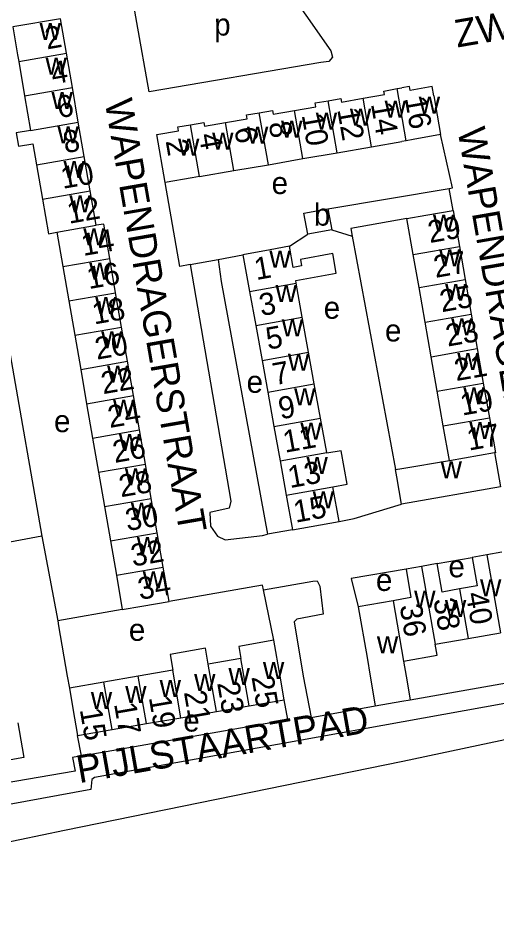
# Model space of a CAD drawing. Extents: x 162883 to 165538, y 383986 to 385172.
# Drawn here: x 164430.6 to 164517.2, y 384254.3 to 384419 of the extents above; entities that cross this region are included whole.
import ezdxf

# ---------------------------------------------------------------- set-up
doc = ezdxf.new("R2010")
doc.units = 0
for name, color, linetype in [('BLT_Basislijn', 7, 'Continuous'), ('BLT_Bebouwing', 7, 'Continuous'), ('BLT_Centroide', 7, 'Continuous'), ('BLT_Huisnummer', 7, 'Continuous'), ('BLT_Huisnummer_ tussenligend', 7, 'Continuous'), ('BLT_Onderverdeling_panden', 7, 'Continuous'), ('BLT_Straatnaam', 7, 'Continuous')]:
    doc.layers.add(name, color=color, linetype=linetype)

msp = doc.modelspace()

# ---------------------------------------------------------------- linework, layer by layer
at = {"layer": 'BLT_Basislijn'}
for p, q in [((164454.29, 384405.7), (164452.06, 384418.28)), ((164485.36, 384411.01), (164454.29, 384405.7)), ((164509.29, 384384.26), (164508.58, 384388.26)), ((164479.71, 384377.78), (164482.99, 384379.97)), ((164487.33, 384380.75), (164491.03, 384379.63)), ((164491.03, 384379.63), (164498.87, 384337.37)), ((164461.74, 384374.47), (164466.77, 384375.41)), ((164466.77, 384375.41), (164471.28, 384376.26)), ((164480.24, 384326.49), (164475.7, 384325.72)), ((164434.9, 384325.32), (164437.76, 384309.99)), ((164506.39, 384320.36), (164512.75, 384321.48)), ((164476.85, 384306.5), (164474.99, 384315.63)), ((164449.44, 384312.07), (164437.76, 384309.99)), ((164501.53, 384295.72), (164537.37, 384302.06)), ((164442.08, 384285.61), (164441.37, 384289.25)), ((164438.99, 384272.13), (164500.18, 384284.61)), ((164379.76, 384259.88), (164438.99, 384272.13))]:
    msp.add_line(p, q, dxfattribs=at)
for points in [[(164452.06, 384418.28), (164451.49, 384421.69), (164451.81, 384423.01), (164453.14, 384423.99), (164474.55, 384427.71), (164476.59, 384427.38), (164478.15, 384426.08), (164487.2, 384413.14), (164487.46, 384412), (164486.84, 384411.19), (164485.36, 384411.01)], [(164508.58, 384388.26), (164509.16, 384388.36), (164507.01, 384397.98)], [(164422.17, 384390.76), (164423.35, 384390.97), (164434.9, 384325.32)], [(164461.74, 384374.47), (164459.85, 384374.11), (164457.21, 384389.3)], [(164486.64, 384384.58), (164508.58, 384388.26)], [(164500.94, 384382.8), (164490.78, 384380.98), (164491.03, 384379.63)], [(164466.77, 384375.41), (164467.34, 384371.42), (164475.7, 384325.72)], [(164461.74, 384374.47), (164469.08, 384331.69), (164468.79, 384330.42), (164465.31, 384329.62), (164465.39, 384327.17), (164466.68, 384325.31), (164468.05, 384324.69), (164474.83, 384325.48), (164475.7, 384325.72)], [(164488.67, 384328.01), (164491.42, 384328.51), (164499.99, 384331.15)], [(164434.9, 384325.32), (164425.15, 384323.55), (164416.49, 384321.97), (164412.07, 384321.15)], [(164500.79, 384319.38), (164490.88, 384317.65), (164492.15, 384312.57)], [(164474.99, 384315.63), (164483.89, 384317.18), (164484.69, 384317.23), (164485.17, 384316.27), (164485.78, 384311.25), (164481, 384310.34), (164480.55, 384309.82), (164482.16, 384300), (164483.59, 384292.55), (164495.22, 384294.64)], [(164474.99, 384315.63), (164474.82, 384316.46), (164457.92, 384313.54)], [(164437.76, 384309.99), (164437.92, 384309.13), (164439.45, 384300), (164439.89, 384297.84)], [(164537.04, 384298.36), (164444.4, 384281.69), (164443.92, 384281.32), (164443.78, 384279.5), (164414.83, 384274.17), (164413.46, 384274.09), (164412.69, 384277.13), (164412.28, 384277.16), (164358.24, 384267.65), (164355.83, 384267.19), (164355.01, 384265.8), (164304.07, 384256.84), (164302.9, 384256.99), (164302.04, 384260.09), (164301.53, 384260.09), (164267.64, 384254.3)], [(164500.18, 384284.61), (164529.46, 384290.85), (164557.72, 384296.7), (164568.34, 384299.01)], [(164442.08, 384285.61), (164479.42, 384292.18), (164478.74, 384295.73)], [(164442.08, 384285.61), (164440.43, 384285.28), (164440.9, 384282.79), (164419.36, 384279.14), (164418.31, 384285.79)]]:
    msp.add_lwpolyline(points, dxfattribs=at)
at = {"layer": 'BLT_Bebouwing'}
for p, q in [((164438.25, 384418.95), (164429.62, 384417.45)), ((164439.33, 384412.71), (164438.25, 384418.95)), ((164430.7, 384411.22), (164431.78, 384404.98)), ((164440.41, 384406.48), (164439.33, 384412.71)), ((164441.49, 384400.25), (164440.41, 384406.48)), ((164496.76, 384405.84), (164499.15, 384406.3)), ((164499.15, 384406.3), (164500, 384406.45)), ((164431.78, 384404.98), (164432.86, 384398.75)), ((164505.79, 384404.97), (164507.01, 384397.98)), ((164442.57, 384394.01), (164441.49, 384400.25)), ((164457.21, 384389.3), (164455.67, 384397.99)), ((164494.56, 384395.79), (164500.01, 384396.73)), ((164500.79, 384396.87), (164500.01, 384396.73)), ((164482.1, 384393.63), (164488.33, 384394.71)), ((164488.33, 384394.71), (164494.56, 384395.79)), ((164443.65, 384387.78), (164442.57, 384394.01)), ((164475.87, 384392.54), (164482.1, 384393.63)), ((164433.94, 384392.52), (164435.02, 384386.29)), ((164463.41, 384390.38), (164469.64, 384391.46)), ((164469.64, 384391.46), (164475.87, 384392.54)), ((164444.73, 384381.57), (164443.65, 384387.78)), ((164486.64, 384384.58), (164487.33, 384380.75)), ((164509.29, 384384.26), (164510.43, 384377.76)), ((164437.62, 384380.31), (164438.69, 384374.11)), ((164487.33, 384380.75), (164482.99, 384379.97)), ((164510.43, 384377.76), (164511.48, 384371.76)), ((164448.24, 384369.37), (164447.17, 384375.58)), ((164471.28, 384376.26), (164472.48, 384369.6)), ((164503.13, 384370.3), (164502.08, 384376.3)), ((164438.69, 384374.11), (164439.77, 384367.91)), ((164511.48, 384371.76), (164512.57, 384365.51)), ((164482.01, 384364.95), (164480.9, 384371.11)), ((164504.23, 384364.05), (164503.13, 384370.3)), ((164449.32, 384363.17), (164448.24, 384369.37)), ((164472.48, 384369.6), (164473.59, 384363.44)), ((164439.77, 384367.91), (164440.84, 384361.7)), ((164512.57, 384365.51), (164513.67, 384359.26)), ((164473.59, 384363.44), (164474.73, 384357.11)), ((164483.15, 384358.62), (164482.01, 384364.95)), ((164505.33, 384357.79), (164504.23, 384364.05)), ((164440.84, 384361.7), (164441.92, 384355.5)), ((164450.39, 384356.97), (164449.32, 384363.17)), ((164484.18, 384352.9), (164483.15, 384358.62)), ((164513.67, 384359.26), (164514.76, 384353.01)), ((164451.46, 384350.76), (164450.39, 384356.97)), ((164474.73, 384357.11), (164475.76, 384351.38)), ((164506.43, 384351.54), (164505.33, 384357.79)), ((164441.92, 384355.5), (164442.99, 384349.29)), ((164485.31, 384346.68), (164484.18, 384352.9)), ((164514.76, 384353.01), (164515.86, 384346.76)), ((164452.54, 384344.56), (164451.46, 384350.76)), ((164475.76, 384351.38), (164476.88, 384345.16)), ((164507.52, 384345.29), (164506.43, 384351.54)), ((164442.99, 384349.29), (164444.07, 384343.09)), ((164486.43, 384340.46), (164485.31, 384346.68)), ((164508.62, 384339.04), (164507.52, 384345.29)), ((164453.62, 384338.35), (164452.54, 384344.56)), ((164476.88, 384345.16), (164478, 384338.94)), ((164444.07, 384343.09), (164445.14, 384336.89)), ((164478, 384338.94), (164479.12, 384332.72)), ((164500, 384337.57), (164508.62, 384339.04)), ((164454.69, 384332.15), (164453.62, 384338.35)), ((164498.87, 384337.37), (164500, 384337.57)), ((164445.14, 384336.89), (164446.22, 384330.68)), ((164488.67, 384328.01), (164487.55, 384334.24)), ((164455.77, 384325.95), (164454.69, 384332.15)), ((164479.12, 384332.72), (164480.24, 384326.49)), ((164446.22, 384330.68), (164447.29, 384324.48)), ((164480.24, 384326.49), (164488.67, 384328.01)), ((164456.84, 384319.74), (164455.77, 384325.95)), ((164447.29, 384324.48), (164448.37, 384318.27)), ((164518.1, 384322.42), (164515.42, 384321.95)), ((164515.42, 384321.95), (164512.75, 384321.48)), ((164457.92, 384313.54), (164456.84, 384319.74)), ((164503.59, 384319.87), (164500.79, 384319.38)), ((164506.39, 384320.36), (164503.59, 384319.87)), ((164448.37, 384318.27), (164449.44, 384312.07)), ((164500, 384313.93), (164498.44, 384313.65)), ((164498.44, 384313.65), (164492.15, 384312.57)), ((164492.15, 384312.57), (164493.72, 384303.39)), ((164512.03, 384306.83), (164517.88, 384307.86)), ((164506.05, 384305.79), (164512.03, 384306.83)), ((164470.92, 384303.22), (164464.98, 384302.19)), ((164500.31, 384302.72), (164500.78, 384300)), ((164458.57, 384301.08), (164452.34, 384300)), ((164452.34, 384300), (164446.11, 384298.92)), ((164500.78, 384300), (164501.53, 384295.72)), ((164446.11, 384298.92), (164439.89, 384297.84)), ((164466.47, 384293.6), (164472.4, 384294.63)), ((164472.4, 384294.63), (164478.74, 384295.73)), ((164460.06, 384292.49), (164466.47, 384293.6)), ((164447.6, 384290.33), (164453.83, 384291.41)), ((164453.83, 384291.41), (164460.06, 384292.49)), ((164441.37, 384289.25), (164447.6, 384290.33))]:
    msp.add_line(p, q, dxfattribs=at)
for points in [[(164429.62, 384417.45), (164430.49, 384412.44), (164430.7, 384411.22)], [(164505.79, 384404.97), (164505.49, 384406.68), (164501.51, 384405.98), (164501.38, 384406.7), (164500, 384406.45)], [(164486.69, 384404.11), (164489, 384404.51), (164489.12, 384403.86), (164493.04, 384404.55)], [(164493.04, 384404.55), (164496.87, 384405.21), (164496.76, 384405.84)], [(164480.58, 384402.33), (164484.45, 384403), (164484.33, 384403.7), (164486.69, 384404.11)], [(164468.12, 384400.16), (164472.04, 384400.84), (164471.92, 384401.54), (164474.23, 384401.94)], [(164474.23, 384401.94), (164476.64, 384402.35), (164476.76, 384401.66), (164480.58, 384402.33)], [(164455.67, 384397.99), (164459.59, 384398.68), (164459.47, 384399.36), (164461.77, 384399.77)], [(164461.77, 384399.77), (164464.21, 384400.19), (164464.33, 384399.5), (164468.12, 384400.16)], [(164432.86, 384398.75), (164430.25, 384398.29), (164430.67, 384395.88), (164433.28, 384396.34), (164433.94, 384392.52)], [(164507.01, 384397.98), (164502.09, 384397.1), (164500.79, 384396.87)], [(164463.41, 384390.38), (164462.1, 384390.16), (164457.21, 384389.3)], [(164435.02, 384386.29), (164436.1, 384380.05), (164437.62, 384380.31)], [(164482.99, 384379.97), (164482.3, 384383.79), (164486.64, 384384.58)], [(164500.94, 384382.8), (164504.36, 384383.4), (164509.29, 384384.26)], [(164447.17, 384375.58), (164446.09, 384381.8), (164444.73, 384381.57)], [(164502.08, 384376.3), (164500.94, 384382.8)], [(164479.71, 384377.78), (164476.2, 384377.15), (164471.28, 384376.26)], [(164480.9, 384371.11), (164480.83, 384371.56), (164488.15, 384372.91), (164487.51, 384376.46), (164481.67, 384375.41), (164481.88, 384374.23), (164480.39, 384373.96), (164479.71, 384377.78)], [(164515.86, 384346.76), (164516.96, 384340.42), (164516.77, 384340.47)], [(164487.55, 384334.24), (164490.16, 384334.71), (164489.07, 384340.8), (164486.45, 384340.32), (164486.43, 384340.46)], [(164516.77, 384340.47), (164517.86, 384334.25), (164499.99, 384331.15)], [(164499.99, 384331.15), (164499.1, 384336.07), (164498.87, 384337.37)], [(164512.75, 384321.48), (164513.65, 384316.33), (164510.47, 384315.78)], [(164500.79, 384319.38), (164501.68, 384314.25), (164500, 384313.93)], [(164510.47, 384315.78), (164507.29, 384315.22), (164506.39, 384320.36)], [(164449.44, 384312.07), (164452.99, 384312.68), (164457.92, 384313.54)], [(164476.85, 384306.5), (164470.55, 384305.38), (164470.92, 384303.22)], [(164478.74, 384295.73), (164478, 384300), (164476.85, 384306.5)], [(164500.31, 384302.72), (164506.4, 384303.8), (164506.05, 384305.79)], [(164464.98, 384302.19), (164464.49, 384305.06), (164458.09, 384303.95), (164458.57, 384301.08)], [(164493.72, 384303.39), (164494.3, 384300), (164495.22, 384294.64)], [(164439.89, 384297.84), (164440.52, 384294.18), (164441.37, 384289.25)], [(164495.22, 384294.64), (164500, 384295.46), (164501.53, 384295.72)], [(164430.53, 384291.56), (164430.77, 384290.18), (164431.62, 384285.26), (164423.18, 384283.79), (164422.7, 384286.55), (164418.31, 384285.79)]]:
    msp.add_lwpolyline(points, dxfattribs=at)
at = {"layer": 'BLT_Onderverdeling_panden'}
for p, q in [((164430.7, 384411.22), (164439.33, 384412.71)), ((164431.78, 384404.98), (164440.41, 384406.48)), ((164500.79, 384396.87), (164499.15, 384406.3)), ((164494.56, 384395.79), (164493.04, 384404.55)), ((164488.33, 384394.71), (164486.69, 384404.11)), ((164475.87, 384392.54), (164474.23, 384401.94)), ((164482.1, 384393.63), (164480.58, 384402.33)), ((164432.86, 384398.75), (164441.49, 384400.25)), ((164463.41, 384390.38), (164461.77, 384399.77)), ((164469.64, 384391.46), (164468.12, 384400.16)), ((164433.94, 384392.52), (164442.57, 384394.01)), ((164435.02, 384386.29), (164443.65, 384387.78)), ((164437.62, 384380.31), (164444.73, 384381.57)), ((164502.08, 384376.3), (164510.43, 384377.76)), ((164438.69, 384374.11), (164447.17, 384375.58)), ((164503.13, 384370.3), (164511.48, 384371.76)), ((164472.48, 384369.6), (164480.9, 384371.11)), ((164439.77, 384367.91), (164448.24, 384369.37)), ((164504.23, 384364.05), (164512.57, 384365.51)), ((164440.84, 384361.7), (164449.32, 384363.17)), ((164474.73, 384357.11), (164483.15, 384358.62)), ((164505.33, 384357.79), (164513.67, 384359.26)), ((164441.92, 384355.5), (164450.39, 384356.97)), ((164475.76, 384351.38), (164484.18, 384352.9)), ((164506.43, 384351.54), (164514.76, 384353.01)), ((164442.99, 384349.29), (164451.46, 384350.76)), ((164476.88, 384345.16), (164485.31, 384346.68)), ((164507.52, 384345.29), (164515.86, 384346.76)), ((164444.07, 384343.09), (164452.54, 384344.56)), ((164478, 384338.94), (164486.43, 384340.46)), ((164508.62, 384339.04), (164516.77, 384340.47)), ((164445.14, 384336.89), (164453.62, 384338.35)), ((164479.12, 384332.72), (164487.55, 384334.24)), ((164446.22, 384330.68), (164454.69, 384332.15)), ((164447.29, 384324.48), (164455.77, 384325.95)), ((164515.42, 384321.95), (164517.88, 384307.86)), ((164448.37, 384318.27), (164456.84, 384319.74)), ((164503.59, 384319.87), (164506.05, 384305.79)), ((164510.47, 384315.78), (164512.03, 384306.83)), ((164498.44, 384313.65), (164500.31, 384302.72)), ((164472.4, 384294.63), (164470.92, 384303.22)), ((164460.06, 384292.49), (164458.57, 384301.08)), ((164466.47, 384293.6), (164464.98, 384302.19)), ((164453.83, 384291.41), (164452.34, 384300)), ((164447.6, 384290.33), (164446.11, 384298.92))]:
    msp.add_line(p, q, dxfattribs=at)
msp.add_lwpolyline([(164473.59, 384363.44), (164482.01, 384364.95)], dxfattribs=at)

# ---------------------------------------------------------------- texts
at = {"layer": 'BLT_Centroide'}
for s, p in [('w', (164434.48, 384415.09)), ('p', (164466.07, 384415.9)), ('w', (164435.55, 384408.84)), ('w', (164436.63, 384402.62)), ('w', (164503.08, 384401.77)), ('w', (164496.91, 384401.03)), ('w', (164484.45, 384398.88)), ('w', (164490.62, 384399.61)), ('w', (164478.17, 384397.42)), ('w', (164437.72, 384396.38)), ('w', (164465.7, 384395.27)), ('w', (164472, 384396.36)), ('w', (164459.53, 384394.19)), ('w', (164438.8, 384390.16)), ('e', (164476.46, 384387.23)), ('w', (164439.88, 384383.91)), ('b', (164484.11, 384381.51)), ('w', (164505.66, 384380.41)), ('w', (164442.39, 384377.97)), ('w', (164476.05, 384373.91)), ('w', (164506.76, 384374.16)), ('w', (164443.46, 384371.75)), ('w', (164477.17, 384367.69)), ('w', (164507.85, 384367.91)), ('w', (164444.54, 384365.53)), ('e', (164485.89, 384364.67)), ('w', (164478.3, 384361.47)), ('e', (164496.97, 384360.56)), ('w', (164508.95, 384361.66)), ('w', (164445.62, 384359.34)), ('w', (164510.05, 384355.41)), ('w', (164479.41, 384355.25)), ('w', (164446.69, 384353.12)), ('e', (164471.94, 384351.27)), ('w', (164480.53, 384349.03)), ('w', (164511.14, 384349.16)), ('w', (164447.77, 384346.94)), ('e', (164437.09, 384344.15)), ('w', (164481.66, 384342.81)), ('w', (164512.23, 384342.91)), ('w', (164448.84, 384340.72)), ('w', (164482.77, 384336.59)), ('w', (164507.03, 384335.81)), ('w', (164449.91, 384334.53)), ('w', (164483.89, 384330.38)), ('w', (164450.99, 384328.31)), ('w', (164452.06, 384322.12)), ('e', (164508.45, 384317.89)), ('w', (164453.14, 384315.91)), ('e', (164495.33, 384315.42)), ('w', (164514.17, 384314.47)), ('w', (164502.25, 384312.38)), ('w', (164507.81, 384310.7)), ('e', (164450.63, 384306.4)), ('w', (164495.51, 384304.14)), ('w', (164474.89, 384299.48)), ('w', (164468.66, 384298.39)), ('w', (164456.2, 384296.23)), ('w', (164462.44, 384297.33)), ('w', (164449.97, 384295.17)), ('w', (164443.75, 384294.08)), ('e', (164460.47, 384289.98))]:
    msp.add_text(s, height=4, dxfattribs=at).set_placement(p)
at = {"layer": 'BLT_Huisnummer'}
for s, rotation, p in [('2', 9.8291, (164435.82, 384413.38)), ('6', 9.8291, (164437.97, 384400.93)), ('16', 279.8455, (164500.54, 384404.59)), ('10', 279.8455, (164481.89, 384401.53)), ('6', 279.8455, (164469.7, 384399.07)), ('2', 279.8455, (164457.28, 384396.83)), ('10', 9.8291, (164438.68, 384388.16)), ('29', 9.9554, (164505.08, 384378.35)), ('14', 9.8291, (164442.39, 384376.01)), ('1', 10.2054, (164473.69, 384371.65)), ('25', 9.9554, (164507.24, 384365.84)), ('18', 9.8291, (164444.35, 384363.62)), ('5', 10.2054, (164475.8, 384359.05)), ('21', 9.9554, (164509.86, 384353.38)), ('22', 9.8291, (164445.96, 384351.01)), ('9', 10.2054, (164478.07, 384346.45)), ('17', 9.9554, (164512.15, 384340.8)), ('26', 9.8291, (164448.07, 384338.57)), ('15', 10.2054, (164480.79, 384327.75)), ('30', 9.8291, (164450.35, 384326.24)), ('34', 9.8291, (164452.62, 384313.79)), ('38', 279.7157, (164505.71, 384313.84)), ('25', 279.8374, (164472.8, 384299.87)), ('19', 279.8221, (164454.23, 384296.16)), ('15', 279.8221, (164441.74, 384293.97))]:
    msp.add_text(s, height=4, rotation=rotation, dxfattribs=at).set_placement(p)
at = {"layer": 'BLT_Huisnummer_ tussenligend'}
for s, rotation, p in [('4', 9.8291, (164436.91, 384407.06)), ('14', 279.8455, (164494.42, 384403.53)), ('12', 279.8455, (164488.32, 384402.52)), ('8', 279.8455, (164475.91, 384400.06)), ('8', 9.8291, (164439.09, 384394.6)), ('4', 279.8455, (164463.27, 384397.95)), ('12', 9.8291, (164439.81, 384381.84)), ('27', 9.9554, (164506.12, 384372.05)), ('16', 9.8291, (164443.39, 384370.02)), ('3', 10.2054, (164474.58, 384365.14)), ('23', 9.9554, (164508.31, 384359.62)), ('20', 9.8291, (164444.84, 384357.25)), ('7', 10.2054, (164477.01, 384352.62)), ('19', 9.9554, (164510.94, 384347.13)), ('24', 9.8291, (164447.17, 384344.9)), ('11', 10.2054, (164478.88, 384340.41)), ('13', 10.2054, (164479.77, 384334.01)), ('28', 9.8291, (164449.19, 384332.36)), ('32', 9.8291, (164451.36, 384319.81)), ('40', 279.9001, (164511.57, 384314.93)), ('36', 279.7157, (164499.61, 384312.74)), ('23', 279.8221, (164466.6, 384298.77)), ('21', 279.8221, (164460.58, 384297.11)), ('17', 279.8221, (164447.94, 384294.99))]:
    msp.add_text(s, height=4, rotation=rotation, dxfattribs=at).set_placement(p)
at = {"layer": 'BLT_Straatnaam'}
for s, height, rotation, p in [('ZWALUWSTAARTWEG', 5, 9.7726, (164510.03, 384413.72)), ('WAPENDRAGERSTRAAT', 5, 279.8251, (164446.25, 384403.99)), ('WAPENDRAGERSTRAAT', 5, 279.8251, (164510.08, 384398.83)), ('PIJLSTAARTPAD', 4.9999, 9.9788, (164441.64, 384280.63))]:
    msp.add_text(s, height=height, rotation=rotation, dxfattribs=at).set_placement(p)

doc.saveas('drawing.dxf')
